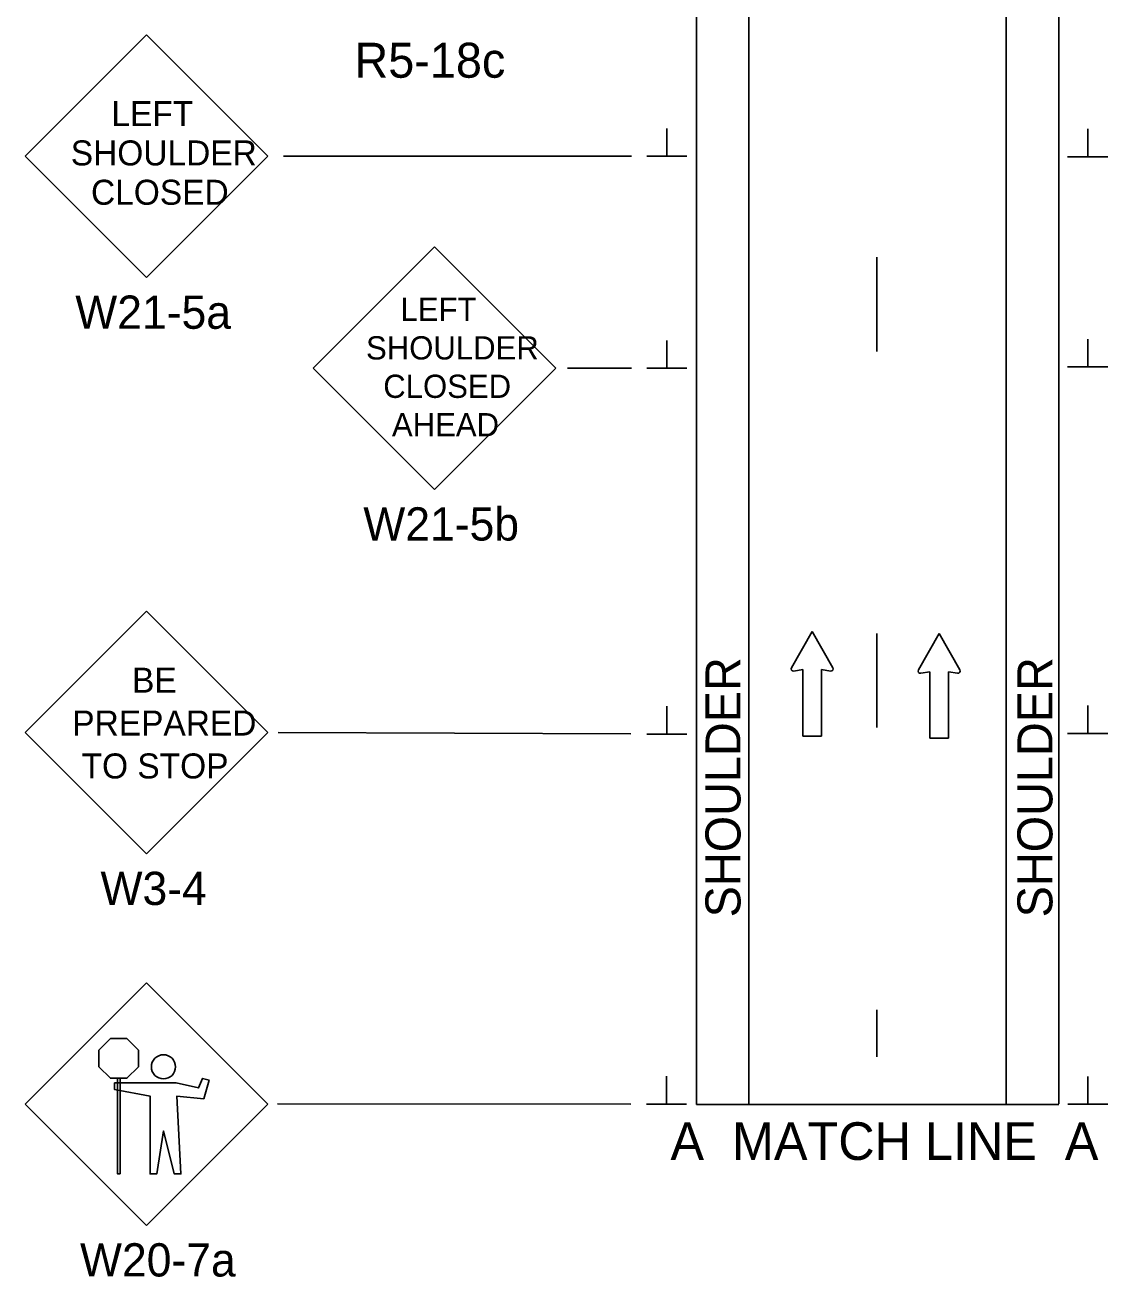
# Model space of a CAD drawing. Extents: x -1809 to 1554, y -1087 to 323.
# Drawn here: x -1669.1 to -1381.5, y -735.9 to -403.2 of the extents above; entities that cross this region are included whole.
import ezdxf

# ---------------------------------------------------------------- set-up
doc = ezdxf.new("R2010")
doc.units = 0
for name, color, linetype in [('BORDER', 7, 'Continuous'), ('BORDER_SIGNAL_WO', 7, 'Continuous'), ('Level 6', 7, 'Continuous'), ('MT_SCRATCH_LEVEL_A', 7, 'Continuous'), ('MT_SCRATCH_LEVEL_E', 7, 'Continuous'), ('PAVT_EDGE_EX', 7, 'Continuous'), ('TRAFFIC_SIGNS_PR', 7, 'Continuous'), ('TYPICAL_EX', 7, 'Continuous'), ('TYPICAL_TEXT_DIMEN_EX', 7, 'Continuous'), ('TYPICAL_TEXT_DIMEN_PR', 7, 'Continuous')]:
    doc.layers.add(name, color=color, linetype=linetype)

msp = doc.modelspace()

# ---------------------------------------------------------------- linework, layer by layer
at = {"layer": 'BORDER'}
msp.add_line((-1408.49, -9.43), (-1408.49, -689.95), dxfattribs=at)
at = {"layer": 'BORDER_SIGNAL_WO'}
for p, q in [((-1442.84, -464.95), (-1442.84, -489.95)), ((-1442.84, -564.95), (-1442.84, -589.95)), ((-1442.84, -664.95), (-1442.84, -677.45))]:
    msp.add_line(p, q, dxfattribs=at)
at = {"layer": 'MT_SCRATCH_LEVEL_A'}
msp.add_line((-1476.89, -9.43), (-1476.89, -689.95), dxfattribs=at)
at = {"layer": 'MT_SCRATCH_LEVEL_E'}
for p, q in [((-1460.06, -564.37), (-1465.54, -574.02)), ((-1454.53, -574.02), (-1460.06, -564.37)), ((-1426.32, -564.95), (-1431.8, -574.6)), ((-1420.79, -574.6), (-1426.32, -564.95)), ((-1464.9, -574.93), (-1462.53, -574.51)), ((-1462.53, -574.51), (-1462.53, -592.19)), ((-1457.54, -592.19), (-1457.54, -574.51)), ((-1457.54, -574.51), (-1455.17, -574.93)), ((-1431.16, -575.51), (-1428.79, -575.09)), ((-1428.79, -575.09), (-1428.79, -592.77)), ((-1423.8, -592.77), (-1423.8, -575.09)), ((-1423.8, -575.09), (-1421.43, -575.51)), ((-1462.53, -592.19), (-1457.54, -592.19)), ((-1428.79, -592.77), (-1423.8, -592.77))]:
    msp.add_line(p, q, dxfattribs=at)
for centre, start, end in [((-1465, -574.32), 150.4248, 279.9638), ((-1455.08, -574.32), 260.0362, 29.7731), ((-1431.26, -574.9), 150.4248, 279.9638), ((-1421.34, -574.9), 260.0362, 29.7731)]:
    msp.add_arc(centre, 0.617, start, end, dxfattribs=at)
at = {"layer": 'PAVT_EDGE_EX'}
for p, q in [((-1490.76, -9.43), (-1490.76, -690.07)), ((-1394.52, -9.43), (-1394.52, -689.95)), ((-1490.76, -690.07), (-1431.79, -690.07)), ((-1431.79, -690.07), (-1394.52, -690.07))]:
    msp.add_line(p, q, dxfattribs=at)
at = {"layer": 'TRAFFIC_SIGNS_PR'}
for p, q in [((-1636.87, -405.87), (-1669.12, -438.12)), ((-1604.63, -438.12), (-1636.87, -405.87)), ((-1669.12, -438.12), (-1636.87, -470.36)), ((-1636.87, -470.36), (-1604.63, -438.12)), ((-1560.36, -462.16), (-1592.6, -494.41)), ((-1528.12, -494.41), (-1560.36, -462.16)), ((-1592.6, -494.41), (-1560.36, -526.65)), ((-1560.36, -526.65), (-1528.12, -494.41)), ((-1636.87, -559.02), (-1669.12, -591.26)), ((-1604.63, -591.26), (-1636.87, -559.02)), ((-1669.12, -591.26), (-1636.87, -623.5)), ((-1636.87, -623.5), (-1604.63, -591.26)), ((-1636.87, -657.75), (-1669.12, -689.99)), ((-1604.63, -689.99), (-1636.87, -657.75)), ((-1669.12, -689.99), (-1636.87, -722.23)), ((-1636.87, -722.23), (-1604.63, -689.99))]:
    msp.add_line(p, q, dxfattribs=at)
for points in [[(-1646.42, -672.61), (-1642.06, -672.61), (-1638.97, -675.7), (-1638.97, -680.06), (-1642.06, -683.14), (-1646.42, -683.14), (-1649.5, -680.06), (-1649.5, -675.7)], [(-1628.94, -684.38), (-1645.35, -684.38), (-1645.35, -686.16), (-1635.89, -687.89), (-1635.89, -708.55), (-1634.11, -708.55), (-1632.33, -697.15), (-1629.48, -708.55), (-1627.7, -708.55), (-1628.77, -687.89), (-1621.64, -688.6), (-1620.22, -683.62), (-1621.95, -683.18), (-1623.01, -685.68)], [(-1644.59, -683.14), (-1644.59, -708.53), (-1643.88, -708.53), (-1643.88, -683.14)]]:
    msp.add_lwpolyline(points, close=True, dxfattribs=at)
msp.add_circle((-1632.35, -680.09), 3.21, dxfattribs=at)
at = {"layer": 'TYPICAL_EX'}
for p, q in [((-1498.62, -438.11), (-1498.62, -430.71)), ((-1386.83, -438.23), (-1386.83, -430.83)), ((-1498.62, -438.11), (-1503.96, -438.11)), ((-1493.28, -438.11), (-1498.62, -438.11)), ((-1386.83, -438.23), (-1392.17, -438.23)), ((-1381.48, -438.23), (-1386.83, -438.23)), ((-1498.63, -494.43), (-1498.63, -487.04)), ((-1386.83, -494.07), (-1386.83, -486.67)), ((-1498.63, -494.43), (-1503.97, -494.43)), ((-1493.28, -494.43), (-1498.63, -494.43)), ((-1386.83, -494.07), (-1392.17, -494.07)), ((-1381.48, -494.07), (-1386.83, -494.07)), ((-1498.63, -591.65), (-1498.63, -584.25)), ((-1386.83, -591.48), (-1386.83, -584.09)), ((-1498.63, -591.65), (-1503.97, -591.65)), ((-1493.28, -591.65), (-1498.63, -591.65)), ((-1386.83, -591.48), (-1392.17, -591.48)), ((-1381.48, -591.48), (-1386.83, -591.48)), ((-1498.73, -689.99), (-1498.73, -682.6)), ((-1386.8, -690.03), (-1386.8, -682.63)), ((-1498.73, -689.99), (-1504.07, -689.99)), ((-1493.38, -689.99), (-1498.73, -689.99)), ((-1386.8, -690.03), (-1392.14, -690.03)), ((-1381.45, -690.03), (-1386.8, -690.03))]:
    msp.add_line(p, q, dxfattribs=at)
at = {"layer": 'TYPICAL_TEXT_DIMEN_PR'}
for p, q in [((-1508.03, -438.11), (-1600.43, -438.12)), ((-1508.05, -494.43), (-1525.05, -494.41)), ((-1508.19, -591.63), (-1601.89, -591.26)), ((-1508.23, -689.99), (-1602.05, -689.95))]:
    msp.add_line(p, q, dxfattribs=at)

# ---------------------------------------------------------------- texts
at = {"layer": 'Level 6'}
msp.add_text('W21-5b', height=8.835, dxfattribs=at).set_placement((-1579.26, -540.23))
at = {"layer": 'TRAFFIC_SIGNS_PR'}
for s, height, p in [('R5-18c', 9.3, (-1581.62, -417.23)), ('LEFT', 6.65, (-1646.18, -430.09)), ('SHOULDER', 6.65, (-1656.97, -440.54)), ('CLOSED', 6.65, (-1651.6, -450.99)), ('W21-5a', 8.835, (-1655.78, -483.95)), ('LEFT', 6.175, (-1569.39, -481.9)), ('SHOULDER', 6.175, (-1578.54, -492.11)), ('CLOSED', 6.175, (-1573.96, -502.32)), ('AHEAD', 6.175, (-1571.66, -512.53)), ('BE', 6.65, (-1640.69, -580.66)), ('PREPARED', 6.65, (-1656.57, -592.06)), ('TO STOP', 6.65, (-1654.1, -603.46)), ('W3-4', 8.835, (-1649.07, -637.09)), ('W20-7a', 8.835, (-1654.52, -735.82))]:
    msp.add_text(s, height=height, dxfattribs=at).set_placement(p)
at = {"layer": 'TYPICAL_TEXT_DIMEN_EX'}
for p in [(-1479.07, -640.37), (-1396.21, -640.37)]:
    msp.add_text('SHOULDER', height=9.305, rotation=90, dxfattribs=at).set_placement(p)
msp.add_text('A  MATCH LINE  A', height=10, dxfattribs=at).set_placement((-1497.67, -704.84))

doc.saveas('drawing.dxf')
